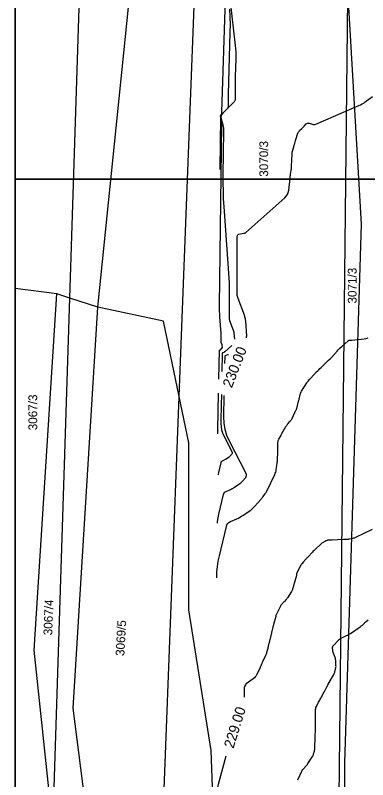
# Model space of a CAD drawing. Extents: x -534410 to -534262, y -1190162 to -1189584.
# Drawn here: x -534410.1 to -534375.9, y -1189747.8 to -1189673.6 of the extents above; entities that cross this region are included whole.
import ezdxf

# ---------------------------------------------------------------- set-up
doc = ezdxf.new("R2010")
doc.units = 0
for name, color, linetype in [('30', 7, 'Continuous'), ('31', 7, 'Continuous'), ('40', 7, 'Continuous'), ('_rámeček', 7, 'Continuous'), ('_rámeček_mřížka', 7, 'Continuous'), ('Hranice parcel', 7, 'Continuous'), ('Parcelní čísla', 7, 'Continuous')]:
    doc.layers.add(name, color=color, linetype=linetype)

msp = doc.modelspace()

# ---------------------------------------------------------------- linework, layer by layer
at = {"layer": '30'}
for points in [[(-534390.347, -1189708.884), (-534390.297, -1189706.091), (-534390.296, -1189706.085), (-534390.293, -1189706.08), (-534390.289, -1189706.076), (-534390.283, -1189706.073), (-534390.257, -1189706.064), (-534390.251, -1189706.061), (-534390.245, -1189706.058), (-534390.239, -1189706.054), (-534390.233, -1189706.05), (-534390.012, -1189705.849), (-534390.01, -1189705.846), (-534390.01, -1189705.836), (-534390.009, -1189705.834), (-534390.007, -1189705.824), (-534390.007, -1189705.818), (-534390.02, -1189705.611), (-534390.021, -1189705.605), (-534390.021, -1189705.599), (-534390.023, -1189705.592), (-534390.024, -1189705.586), (-534390.03, -1189705.562), (-534390.031, -1189705.556), (-534390.033, -1189705.55), (-534390.035, -1189705.544), (-534390.037, -1189705.538), (-534390.123, -1189705.312), (-534390.127, -1189705.298), (-534390.13, -1189705.285), (-534390.132, -1189705.271), (-534390.133, -1189705.257), (-534390.133, -1189705.161), (-534390.133, -1189705.109), (-534390.133, -1189704.996), (-534390.133, -1189704.885), (-534390.133, -1189704.834), (-534390.133, -1189704.721), (-534390.133, -1189704.61), (-534390.133, -1189704.558), (-534390.133, -1189704.487), (-534390.133, -1189704.473), (-534390.133, -1189704.459), (-534390.134, -1189704.445), (-534390.135, -1189704.431), (-534390.247, -1189702.817), (-534390.263, -1189702.543), (-534390.273, -1189702.269), (-534390.278, -1189701.995), (-534390.277, -1189701.721), (-534390.042, -1189684.12), (-534390.043, -1189684.036), (-534390.05, -1189683.951), (-534390.063, -1189683.868), (-534390.081, -1189683.785), (-534390.164, -1189683.455), (-534390.175, -1189683.375), (-534390.165, -1189683.301), (-534390.135, -1189683.232), (-534390.085, -1189683.169), (-534389.476, -1189682.56), (-534389.452, -1189682.531), (-534389.435, -1189682.5), (-534389.425, -1189682.466), (-534389.422, -1189682.43), (-534389.422, -1189682.277), (-534389.422, -1189682.201), (-534389.422, -1189682.125), (-534389.422, -1189681.932), (-534389.422, -1189681.826), (-534389.422, -1189681.651), (-534389.422, -1189681.545), (-534389.422, -1189681.387), (-534389.422, -1189681.349), (-534389.422, -1189681.311), (-534389.421, -1189681.273), (-534389.42, -1189681.235), (-534389.233, -1189675.203), (-534389.223, -1189674.453), (-534389.24, -1189673.705), (-534389.285, -1189672.958)], [(-534387.663, -1189704.868), (-534387.663, -1189704.864), (-534387.662, -1189704.854), (-534387.661, -1189704.845), (-534387.66, -1189704.835), (-534387.658, -1189704.825), (-534387.646, -1189704.767), (-534387.643, -1189704.754), (-534387.642, -1189704.741), (-534387.641, -1189704.728), (-534387.642, -1189704.715), (-534387.737, -1189703.209), (-534387.741, -1189703.164), (-534387.747, -1189703.118), (-534387.754, -1189703.073), (-534387.764, -1189703.029), (-534387.805, -1189702.851), (-534387.816, -1189702.806), (-534387.829, -1189702.762), (-534387.843, -1189702.719), (-534387.859, -1189702.676), (-534388.484, -1189701.034), (-534388.516, -1189700.939), (-534388.538, -1189700.841), (-534388.552, -1189700.742), (-534388.556, -1189700.641), (-534388.556, -1189700.125), (-534388.556, -1189700.032), (-534388.556, -1189699.938), (-534388.556, -1189699.704), (-534388.556, -1189699.611), (-534388.556, -1189699.564), (-534388.556, -1189699.048), (-534388.556, -1189698.946), (-534388.556, -1189698.845), (-534388.556, -1189698.743), (-534388.556, -1189698.641), (-534388.556, -1189698.125), (-534388.556, -1189698.032), (-534388.556, -1189697.938), (-534388.556, -1189697.704), (-534388.556, -1189697.611), (-534388.556, -1189697.564), (-534388.556, -1189697.048), (-534388.556, -1189696.946), (-534388.556, -1189696.845), (-534388.556, -1189696.743), (-534388.556, -1189696.641), (-534388.556, -1189696.125), (-534388.556, -1189696.032), (-534388.556, -1189695.938), (-534388.556, -1189695.704), (-534388.556, -1189695.611), (-534388.556, -1189695.564), (-534388.556, -1189695.016), (-534388.546, -1189694.938), (-534388.515, -1189694.878), (-534388.462, -1189694.835), (-534388.389, -1189694.808), (-534387.924, -1189694.707), (-534387.906, -1189694.704), (-534387.888, -1189694.7), (-534387.87, -1189694.697), (-534387.852, -1189694.694), (-534387.779, -1189694.683), (-534387.762, -1189694.68), (-534387.745, -1189694.673), (-534387.73, -1189694.665), (-534387.716, -1189694.654), (-534383.944, -1189691.283), (-534383.793, -1189691.123), (-534383.678, -1189690.944), (-534383.599, -1189690.747), (-534383.556, -1189690.532), (-534383.427, -1189689.383), (-534383.415, -1189689.283), (-534383.403, -1189689.183), (-534383.389, -1189689.084), (-534383.375, -1189688.984), (-534383.316, -1189688.586), (-534383.302, -1189688.487), (-534383.291, -1189688.387), (-534383.283, -1189688.287), (-534383.278, -1189688.186), (-534383.231, -1189687.038), (-534383.224, -1189686.942), (-534383.211, -1189686.847), (-534383.192, -1189686.752), (-534383.168, -1189686.659), (-534383.03, -1189686.202), (-534383.016, -1189686.152), (-534383.001, -1189686.101), (-534382.987, -1189686.051), (-534382.973, -1189686), (-534382.92, -1189685.797), (-534382.906, -1189685.746), (-534382.891, -1189685.695), (-534382.876, -1189685.645), (-534382.86, -1189685.595), (-534382.658, -1189684.99), (-534382.63, -1189684.92), (-534382.594, -1189684.854), (-534382.55, -1189684.794), (-534382.499, -1189684.739), (-534382.276, -1189684.528), (-534382.221, -1189684.475), (-534382.167, -1189684.421), (-534382.113, -1189684.367), (-534382.06, -1189684.311), (-534381.849, -1189684.089), (-534381.793, -1189684.043), (-534381.733, -1189684.017), (-534381.668, -1189684.011), (-534381.597, -1189684.024), (-534381.25, -1189684.135), (-534381.168, -1189684.153), (-534381.087, -1189684.157), (-534381.007, -1189684.146), (-534380.927, -1189684.119), (-534376.732, -1189682.324), (-534376.571, -1189682.249), (-534376.415, -1189682.164), (-534376.265, -1189682.07), (-534376.121, -1189681.967), (-534375.412, -1189681.425)], [(-534389.758, -1189707.367), (-534389.745, -1189706.698), (-534389.738, -1189706.652), (-534389.72, -1189706.614), (-534389.69, -1189706.584), (-534389.648, -1189706.563), (-534389.457, -1189706.496), (-534389.413, -1189706.478)], [(-534390.482, -1189722.874), (-534390.465, -1189722.694), (-534390.412, -1189722.337), (-534390.339, -1189721.983), (-534389.891, -1189720.084), (-534389.856, -1189719.981), (-534389.8, -1189719.895), (-534389.725, -1189719.825), (-534389.63, -1189719.771), (-534389.213, -1189719.588), (-534389.11, -1189719.54), (-534389.009, -1189719.488), (-534388.911, -1189719.431), (-534388.816, -1189719.369), (-534388.404, -1189719.089), (-534388.309, -1189719.02), (-534388.218, -1189718.945), (-534388.133, -1189718.865), (-534388.052, -1189718.779), (-534387.739, -1189718.424), (-534387.677, -1189718.333), (-534387.648, -1189718.238), (-534387.653, -1189718.139), (-534387.691, -1189718.036), (-534389.307, -1189714.911), (-534389.557, -1189714.347), (-534389.732, -1189713.765), (-534389.833, -1189713.165), (-534389.858, -1189712.549), (-534389.818, -1189710.468)], [(-534390.444, -1189714.199), (-534390.442, -1189713.921), (-534390.442, -1189713.914), (-534390.438, -1189713.899), (-534390.436, -1189713.897), (-534390.431, -1189713.895), (-534390.426, -1189713.891), (-534390.423, -1189713.887), (-534390.424, -1189713.886), (-534390.434, -1189713.865), (-534390.436, -1189713.862), (-534390.437, -1189713.858), (-534390.438, -1189713.854), (-534390.438, -1189713.85), (-534390.437, -1189713.799), (-534390.372, -1189710.252)], [(-534375.433, -1189723.48), (-534377.082, -1189724.25), (-534377.145, -1189724.277), (-534377.209, -1189724.302), (-534377.274, -1189724.323), (-534377.341, -1189724.34), (-534377.646, -1189724.413), (-534377.695, -1189724.423), (-534377.744, -1189724.431), (-534377.793, -1189724.436), (-534377.843, -1189724.438), (-534378.042, -1189724.444), (-534378.092, -1189724.445), (-534378.141, -1189724.447), (-534378.191, -1189724.449), (-534378.241, -1189724.451), (-534379.33, -1189724.51), (-534379.372, -1189724.512), (-534379.413, -1189724.514), (-534379.454, -1189724.515), (-534379.495, -1189724.517), (-534379.678, -1189724.522), (-534379.71, -1189724.523), (-534379.743, -1189724.527), (-534379.774, -1189724.533), (-534379.806, -1189724.541), (-534379.932, -1189724.576), (-534379.963, -1189724.585), (-534379.993, -1189724.598), (-534380.022, -1189724.612), (-534380.05, -1189724.628), (-534380.289, -1189724.782), (-534380.337, -1189724.814), (-534380.384, -1189724.849), (-534380.429, -1189724.886), (-534380.472, -1189724.925), (-534380.91, -1189725.339), (-534380.997, -1189725.422), (-534381.082, -1189725.506), (-534381.166, -1189725.591), (-534381.249, -1189725.678), (-534381.665, -1189726.118), (-534381.704, -1189726.159), (-534381.743, -1189726.201), (-534381.781, -1189726.243), (-534381.819, -1189726.285), (-534381.979, -1189726.464), (-534382.013, -1189726.502), (-534382.048, -1189726.54), (-534382.082, -1189726.578), (-534382.117, -1189726.616), (-534382.254, -1189726.768), (-534382.287, -1189726.807), (-534382.317, -1189726.848), (-534382.345, -1189726.891), (-534382.369, -1189726.936), (-534382.785, -1189727.762), (-534382.791, -1189727.776), (-534382.796, -1189727.79), (-534382.799, -1189727.804), (-534382.801, -1189727.819), (-534382.805, -1189727.879), (-534382.806, -1189727.893), (-534382.809, -1189727.908), (-534382.811, -1189727.923), (-534382.815, -1189727.937), (-534383.031, -1189728.712), (-534383.049, -1189728.778), (-534383.068, -1189728.845), (-534383.086, -1189728.911), (-534383.104, -1189728.977), (-534383.177, -1189729.241), (-534383.198, -1189729.306), (-534383.223, -1189729.369), (-534383.253, -1189729.43), (-534383.288, -1189729.489), (-534383.682, -1189730.105), (-534383.713, -1189730.152), (-534383.747, -1189730.198), (-534383.782, -1189730.243), (-534383.819, -1189730.286), (-534383.979, -1189730.464), (-534384.013, -1189730.502), (-534384.048, -1189730.54), (-534384.082, -1189730.578), (-534384.116, -1189730.616), (-534384.254, -1189730.768), (-534384.287, -1189730.807), (-534384.317, -1189730.848), (-534384.344, -1189730.891), (-534384.369, -1189730.936), (-534384.785, -1189731.762), (-534384.791, -1189731.776), (-534384.796, -1189731.79), (-534384.799, -1189731.804), (-534384.801, -1189731.819), (-534384.805, -1189731.879), (-534384.806, -1189731.893), (-534384.808, -1189731.908), (-534384.811, -1189731.923), (-534384.815, -1189731.937), (-534385.03, -1189732.709), (-534385.049, -1189732.777), (-534385.066, -1189732.845), (-534385.084, -1189732.913), (-534385.1, -1189732.981), (-534385.165, -1189733.253), (-534385.182, -1189733.322), (-534385.198, -1189733.39), (-534385.214, -1189733.458), (-534385.231, -1189733.526), (-534385.476, -1189734.53), (-534385.491, -1189734.593), (-534385.506, -1189734.656), (-534385.543, -1189734.807), (-534385.547, -1189734.826), (-534385.552, -1189734.844), (-534385.557, -1189734.863), (-534385.562, -1189734.882), (-534385.582, -1189734.958), (-534385.592, -1189734.995), (-534385.602, -1189735.033), (-534385.705, -1189735.424), (-534385.726, -1189735.495), (-534385.749, -1189735.565), (-534385.776, -1189735.633), (-534385.806, -1189735.701), (-534386.105, -1189736.336), (-534386.128, -1189736.386), (-534386.151, -1189736.436), (-534386.172, -1189736.487), (-534386.193, -1189736.538), (-534386.274, -1189736.742), (-534386.295, -1189736.793), (-534386.316, -1189736.844), (-534386.339, -1189736.894), (-534386.362, -1189736.944), (-534386.663, -1189737.567), (-534386.728, -1189737.683), (-534386.804, -1189737.787), (-534386.894, -1189737.882), (-534386.995, -1189737.966), (-534387.694, -1189738.476), (-534387.717, -1189738.496), (-534387.738, -1189738.517), (-534387.756, -1189738.541), (-534387.772, -1189738.567), (-534387.844, -1189738.704), (-534387.85, -1189738.717), (-534387.856, -1189738.73), (-534387.861, -1189738.744), (-534387.865, -1189738.758), (-534387.879, -1189738.816), (-534387.882, -1189738.83), (-534387.884, -1189738.845), (-534387.885, -1189738.859), (-534387.885, -1189738.874), (-534387.885, -1189739.769)], [(-534389.675, -1189745.496), (-534390.401, -1189748.249), (-534390.532, -1189748.817), (-534390.627, -1189749.39), (-534390.685, -1189749.968)]]:
    msp.add_lwpolyline(points, dxfattribs=at)
at = {"layer": '31'}
for points in [[(-534389.579, -1189669.318), (-534388.753, -1189676.5), (-534388.722, -1189676.816), (-534388.703, -1189677.132), (-534388.696, -1189677.448), (-534388.7, -1189677.765), (-534388.755, -1189679.527), (-534388.757, -1189679.597), (-534388.758, -1189679.667), (-534388.759, -1189679.736), (-534388.759, -1189679.806), (-534388.759, -1189680.095), (-534388.759, -1189680.224), (-534388.759, -1189680.353), (-534388.759, -1189680.61), (-534388.759, -1189680.739), (-534388.759, -1189680.868), (-534388.759, -1189681.157), (-534388.759, -1189681.227), (-534388.759, -1189681.297), (-534388.759, -1189681.366), (-534388.759, -1189681.436), (-534388.759, -1189681.715), (-534388.765, -1189681.782), (-534388.783, -1189681.844), (-534388.814, -1189681.901), (-534388.857, -1189681.953), (-534389.973, -1189683.069), (-534390.065, -1189683.184), (-534390.12, -1189683.31), (-534390.137, -1189683.446), (-534390.118, -1189683.592), (-534389.965, -1189684.197), (-534389.932, -1189684.348), (-534389.909, -1189684.501), (-534389.896, -1189684.656), (-534389.893, -1189684.811), (-534389.95, -1189689.079), (-534389.953, -1189689.842), (-534389.939, -1189690.605), (-534389.91, -1189691.367), (-534389.865, -1189692.129), (-534389.353, -1189699.537), (-534389.349, -1189699.594), (-534389.347, -1189699.652), (-534389.345, -1189699.71), (-534389.345, -1189699.767), (-534389.344, -1189700.088), (-534389.344, -1189700.168), (-534389.344, -1189700.327), (-534389.344, -1189700.38), (-534389.345, -1189700.674), (-534389.345, -1189700.732), (-534389.345, -1189700.79), (-534389.345, -1189700.847), (-534389.345, -1189700.905), (-534389.344, -1189701.225), (-534389.344, -1189701.305), (-534389.344, -1189701.465), (-534389.344, -1189701.518), (-534389.345, -1189701.812), (-534389.345, -1189701.869), (-534389.345, -1189701.927), (-534389.345, -1189701.985), (-534389.345, -1189702.043), (-534389.344, -1189702.363), (-534389.344, -1189702.443), (-534389.344, -1189702.603), (-534389.344, -1189702.656), (-534389.345, -1189702.949), (-534389.342, -1189703.007), (-534389.334, -1189703.063), (-534389.322, -1189703.119), (-534389.304, -1189703.173), (-534388.948, -1189704.107), (-534388.939, -1189704.131), (-534388.931, -1189704.156), (-534388.924, -1189704.181), (-534388.917, -1189704.206), (-534388.894, -1189704.308), (-534388.888, -1189704.333), (-534388.884, -1189704.359), (-534388.881, -1189704.384), (-534388.879, -1189704.41), (-534388.841, -1189705.007)], [(-534389.712, -1189670.951), (-534390.085, -1189682.943), (-534390.085, -1189682.962), (-534390.085, -1189683.066), (-534390.085, -1189683.119), (-534390.085, -1189683.144), (-534390.086, -1189683.15), (-534390.088, -1189683.156), (-534390.09, -1189683.161), (-534390.094, -1189683.166), (-534390.197, -1189683.269), (-534390.206, -1189683.28), (-534390.211, -1189683.291), (-534390.212, -1189683.304), (-534390.211, -1189683.317), (-534390.197, -1189683.373), (-534390.194, -1189683.387), (-534390.191, -1189683.401), (-534390.19, -1189683.415), (-534390.19, -1189683.43), (-534390.258, -1189688.509)], [(-534390.545, -1189728.162), (-534390.526, -1189727.621), (-534390.477, -1189727.083), (-534390.398, -1189726.549), (-534390.288, -1189726.018), (-534389.618, -1189723.176), (-534389.564, -1189723.023), (-534389.481, -1189722.893), (-534389.369, -1189722.788), (-534389.227, -1189722.708), (-534388.603, -1189722.434), (-534388.448, -1189722.362), (-534388.298, -1189722.284), (-534388.151, -1189722.198), (-534388.008, -1189722.106), (-534387.392, -1189721.688), (-534387.249, -1189721.584), (-534387.114, -1189721.472), (-534386.986, -1189721.352), (-534386.865, -1189721.223), (-534386.273, -1189720.552), (-534386.218, -1189720.489), (-534386.164, -1189720.424), (-534386.11, -1189720.359), (-534386.057, -1189720.293), (-534385.848, -1189720.029), (-534385.797, -1189719.961), (-534385.751, -1189719.891), (-534385.709, -1189719.819), (-534385.671, -1189719.744), (-534384.914, -1189718.143), (-534384.862, -1189718.021), (-534384.819, -1189717.896), (-534384.786, -1189717.768), (-534384.763, -1189717.637), (-534384.683, -1189717.063), (-534384.67, -1189716.953), (-534384.659, -1189716.844), (-534384.651, -1189716.734), (-534384.645, -1189716.625), (-534384.625, -1189716.024), (-534384.624, -1189715.994), (-534384.624, -1189715.964), (-534384.623, -1189715.934), (-534384.623, -1189715.904), (-534384.623, -1189715.785), (-534384.623, -1189715.755), (-534384.623, -1189715.725), (-534384.622, -1189715.695), (-534384.621, -1189715.665), (-534384.6, -1189715.001), (-534384.593, -1189714.924), (-534384.577, -1189714.849), (-534384.553, -1189714.777), (-534384.519, -1189714.708), (-534384.366, -1189714.435), (-534384.328, -1189714.367), (-534384.289, -1189714.298), (-534384.251, -1189714.23), (-534384.212, -1189714.162), (-534383.825, -1189713.479), (-534383.782, -1189713.408), (-534383.736, -1189713.34), (-534383.685, -1189713.275), (-534383.631, -1189713.212), (-534383.408, -1189712.967), (-534383.355, -1189712.904), (-534383.308, -1189712.837), (-534383.266, -1189712.767), (-534383.23, -1189712.693), (-534382.975, -1189712.114), (-534382.959, -1189712.08), (-534382.943, -1189712.047), (-534382.926, -1189712.015), (-534382.908, -1189711.983), (-534382.833, -1189711.855), (-534382.816, -1189711.823), (-534382.8, -1189711.79), (-534382.788, -1189711.756), (-534382.777, -1189711.721), (-534382.593, -1189711.007), (-534382.572, -1189710.926), (-534382.551, -1189710.844), (-534382.531, -1189710.763), (-534382.512, -1189710.681), (-534382.434, -1189710.355), (-534382.412, -1189710.275), (-534382.383, -1189710.197), (-534382.348, -1189710.122), (-534382.307, -1189710.05), (-534381.796, -1189709.229), (-534381.769, -1189709.187), (-534381.74, -1189709.146), (-534381.709, -1189709.107), (-534381.676, -1189709.069), (-534381.541, -1189708.919), (-534381.508, -1189708.882), (-534381.474, -1189708.845), (-534381.439, -1189708.808), (-534381.405, -1189708.772), (-534380.842, -1189708.178), (-534380.736, -1189708.068), (-534380.628, -1189707.959), (-534380.52, -1189707.852), (-534380.409, -1189707.746), (-534379.812, -1189707.179), (-534379.778, -1189707.146), (-534379.744, -1189707.113), (-534379.71, -1189707.08), (-534379.676, -1189707.046), (-534379.541, -1189706.912), (-534379.508, -1189706.878), (-534379.475, -1189706.844), (-534379.443, -1189706.809), (-534379.411, -1189706.774), (-534378.862, -1189706.158), (-534378.758, -1189706.046), (-534378.652, -1189705.936), (-534378.542, -1189705.829), (-534378.429, -1189705.726), (-534377.789, -1189705.154), (-534377.765, -1189705.136), (-534377.739, -1189705.122), (-534377.712, -1189705.112), (-534377.682, -1189705.107), (-534377.561, -1189705.094), (-534377.531, -1189705.091), (-534377.5, -1189705.088), (-534377.47, -1189705.084), (-534377.439, -1189705.081), (-534376.24, -1189704.963), (-534376.037, -1189704.926), (-534375.85, -1189704.857)], [(-534389.07, -1189705.596), (-534389.76, -1189706.222), (-534389.782, -1189706.241), (-534389.806, -1189706.256), (-534389.831, -1189706.269), (-534389.857, -1189706.28), (-534389.965, -1189706.318), (-534389.989, -1189706.33), (-534390.006, -1189706.347), (-534390.017, -1189706.368), (-534390.021, -1189706.395), (-534390.052, -1189708.124)], [(-534390.093, -1189710.361), (-534390.099, -1189710.657), (-534390.108, -1189711.11), (-534390.148, -1189713.199), (-534390.135, -1189713.51), (-534390.085, -1189713.811), (-534389.997, -1189714.104), (-534389.871, -1189714.388), (-534389.057, -1189715.961), (-534389.038, -1189716.013), (-534389.036, -1189716.063), (-534389.05, -1189716.11), (-534389.081, -1189716.156), (-534389.239, -1189716.335), (-534389.279, -1189716.378), (-534389.323, -1189716.419), (-534389.368, -1189716.456), (-534389.416, -1189716.491), (-534389.623, -1189716.632), (-534389.671, -1189716.663), (-534389.721, -1189716.692), (-534389.771, -1189716.718), (-534389.823, -1189716.742), (-534390.033, -1189716.834), (-534390.081, -1189716.861), (-534390.119, -1189716.897), (-534390.147, -1189716.94), (-534390.165, -1189716.992), (-534390.39, -1189717.947), (-534390.427, -1189718.126), (-534390.44, -1189718.216)], [(-534382.672, -1189747.784), (-534382.664, -1189747.77), (-534382.656, -1189747.756), (-534382.649, -1189747.742), (-534382.642, -1189747.728), (-534382.276, -1189746.925), (-534382.257, -1189746.885), (-534382.234, -1189746.848), (-534382.209, -1189746.813), (-534382.181, -1189746.779), (-534382.063, -1189746.649), (-534382.033, -1189746.616), (-534382.004, -1189746.584), (-534381.974, -1189746.551), (-534381.945, -1189746.518), (-534381.808, -1189746.366), (-534381.776, -1189746.329), (-534381.746, -1189746.291), (-534381.718, -1189746.251), (-534381.691, -1189746.211), (-534381.257, -1189745.532), (-534381.221, -1189745.469), (-534381.189, -1189745.404), (-534381.162, -1189745.337), (-534381.14, -1189745.268), (-534381.062, -1189744.986), (-534381.045, -1189744.915), (-534381.032, -1189744.843), (-534381.023, -1189744.771), (-534381.019, -1189744.698), (-534381.006, -1189744.227), (-534381.004, -1189744.166), (-534381.002, -1189744.104), (-534380.999, -1189744.042), (-534380.996, -1189743.981), (-534380.983, -1189743.734), (-534380.98, -1189743.673), (-534380.977, -1189743.611), (-534380.975, -1189743.55), (-534380.973, -1189743.488), (-534380.961, -1189743.036), (-534380.959, -1189742.94), (-534380.958, -1189742.844), (-534380.957, -1189742.749), (-534380.956, -1189742.653), (-534380.956, -1189742.111), (-534380.956, -1189741.951), (-534380.956, -1189741.631), (-534380.956, -1189741.525), (-534380.956, -1189741.041), (-534380.951, -1189740.944), (-534380.934, -1189740.85), (-534380.906, -1189740.758), (-534380.867, -1189740.669), (-534380.65, -1189740.241), (-534380.599, -1189740.14), (-534380.547, -1189740.04), (-534380.493, -1189739.941), (-534380.439, -1189739.842), (-534380.111, -1189739.248), (-534380.088, -1189739.208), (-534380.066, -1189739.167), (-534380.044, -1189739.127), (-534380.023, -1189739.087), (-534379.905, -1189738.869), (-534379.899, -1189738.857), (-534379.892, -1189738.844), (-534379.886, -1189738.832), (-534379.88, -1189738.819), (-534379.857, -1189738.768), (-534379.851, -1189738.756), (-534379.844, -1189738.743), (-534379.838, -1189738.73), (-534379.832, -1189738.718), (-534379.768, -1189738.593), (-534379.756, -1189738.568), (-534379.742, -1189738.543), (-534379.729, -1189738.518), (-534379.715, -1189738.494), (-534379.199, -1189737.61), (-534379.161, -1189737.539), (-534379.128, -1189737.466), (-534379.1, -1189737.391), (-534379.077, -1189737.314), (-534378.996, -1189737.001), (-534378.979, -1189736.922), (-534378.968, -1189736.843), (-534378.962, -1189736.763), (-534378.963, -1189736.683), (-534378.98, -1189736.278), (-534378.987, -1189736.184), (-534379.002, -1189736.092), (-534379.024, -1189736.001), (-534379.053, -1189735.911), (-534379.229, -1189735.429), (-534379.248, -1189735.373), (-534379.262, -1189735.316), (-534379.273, -1189735.258), (-534379.28, -1189735.199), (-534379.298, -1189734.963), (-534379.297, -1189734.906), (-534379.285, -1189734.853), (-534379.261, -1189734.804), (-534379.226, -1189734.759), (-534378.695, -1189734.203), (-534378.616, -1189734.128), (-534378.531, -1189734.061), (-534378.44, -1189734.003), (-534378.343, -1189733.954), (-534377.943, -1189733.774), (-534377.844, -1189733.726), (-534377.748, -1189733.675), (-534377.653, -1189733.62), (-534377.561, -1189733.561), (-534376.609, -1189732.919), (-534376.554, -1189732.881), (-534376.502, -1189732.84), (-534376.451, -1189732.797), (-534376.402, -1189732.752), (-534376.2, -1189732.558), (-534376.156, -1189732.517), (-534376.111, -1189732.476), (-534376.066, -1189732.436), (-534376.02, -1189732.397), (-534375.836, -1189732.242)]]:
    msp.add_lwpolyline(points, dxfattribs=at)
at = {"layer": '_rámeček'}
msp.add_line((-534410.126, -1189584.47), (-534410.126, -1190161.97), dxfattribs=at)
for points in [[(-534410.126, -1189584.47), (-534261.626, -1189584.47), (-534261.626, -1189689.47), (-534410.126, -1189689.47)], [(-534410.126, -1189689.47), (-534261.626, -1189689.47), (-534261.626, -1189794.47), (-534410.126, -1189794.47)]]:
    msp.add_lwpolyline(points, close=True, dxfattribs=at)
at = {"layer": '_rámeček_mřížka'}
for p, q in [((-534410.126, -1189584.47), (-534410.126, -1190161.97)), ((-534407.126, -1189689.47), (-534410.126, -1189689.47)), ((-534407.126, -1189689.47), (-534410.126, -1189689.47))]:
    msp.add_line(p, q, dxfattribs=at)
at = {"layer": 'Hranice parcel'}
for p, q in [((-534404.82, -1189701), (-534402.64, -1189633.7)), ((-534394.19, -1189710.57), (-534391.41, -1189637.73)), ((-534378.67, -1189750.28), (-534377.8, -1189671.05)), ((-534404.82, -1189701), (-534406.08, -1189700.59)), ((-534406.48, -1189752.31), (-534404.82, -1189701)), ((-534402.1, -1189701.89), (-534404.82, -1189701)), ((-534398.3, -1189817.87), (-534394.19, -1189710.57))]:
    msp.add_line(p, q, dxfattribs=at)
for points in [[(-534402.1, -1189701.89), (-534396.03, -1189642.33), (-534395.58, -1189636.23)], [(-534378.12, -1189750.26), (-534378.12, -1189746.17), (-534376.49, -1189693.82), (-534377.8, -1189671.05)], [(-534406.08, -1189700.59), (-534410.126, -1189700.066)], [(-534406.48, -1189752.31), (-534408.29, -1189735.19), (-534406.08, -1189700.59)], [(-534398.3, -1189817.87), (-534398.2, -1189776.76), (-534402.83, -1189754), (-534404.51, -1189740.82), (-534402.1, -1189701.89)], [(-534394.19, -1189710.57), (-534395.72, -1189703.26), (-534402.1, -1189701.89)], [(-534390.92, -1189749.37), (-534391.09, -1189744.93), (-534393.26, -1189731.27), (-534393.26, -1189715.05), (-534394.19, -1189710.57)]]:
    msp.add_lwpolyline(points, dxfattribs=at)

# ---------------------------------------------------------------- texts
at = {"layer": '40'}
for s, rotation, p in [('230.00', 68.76123, (-534389.089, -1189709.788)), ('229.00', 72.61335, (-534388.93, -1189744.788))]:
    msp.add_text(s, height=1, rotation=rotation, dxfattribs=at).set_placement(p)
at = {"layer": 'Parcelní čísla'}
for s, rotation, p in [('3070/3', 90, (-534385.558, -1189689.227)), ('3071/3', 90, (-534376.962, -1189701.539)), ('3067/3', 90, (-534407.997, -1189713.846)), ('3067/4', 88, (-534406.541, -1189733.76)), ('3069/5', 87, (-534399.532, -1189735.774))]:
    msp.add_text(s, height=0.85, rotation=rotation, dxfattribs=at).set_placement(p)

doc.saveas('drawing.dxf')
